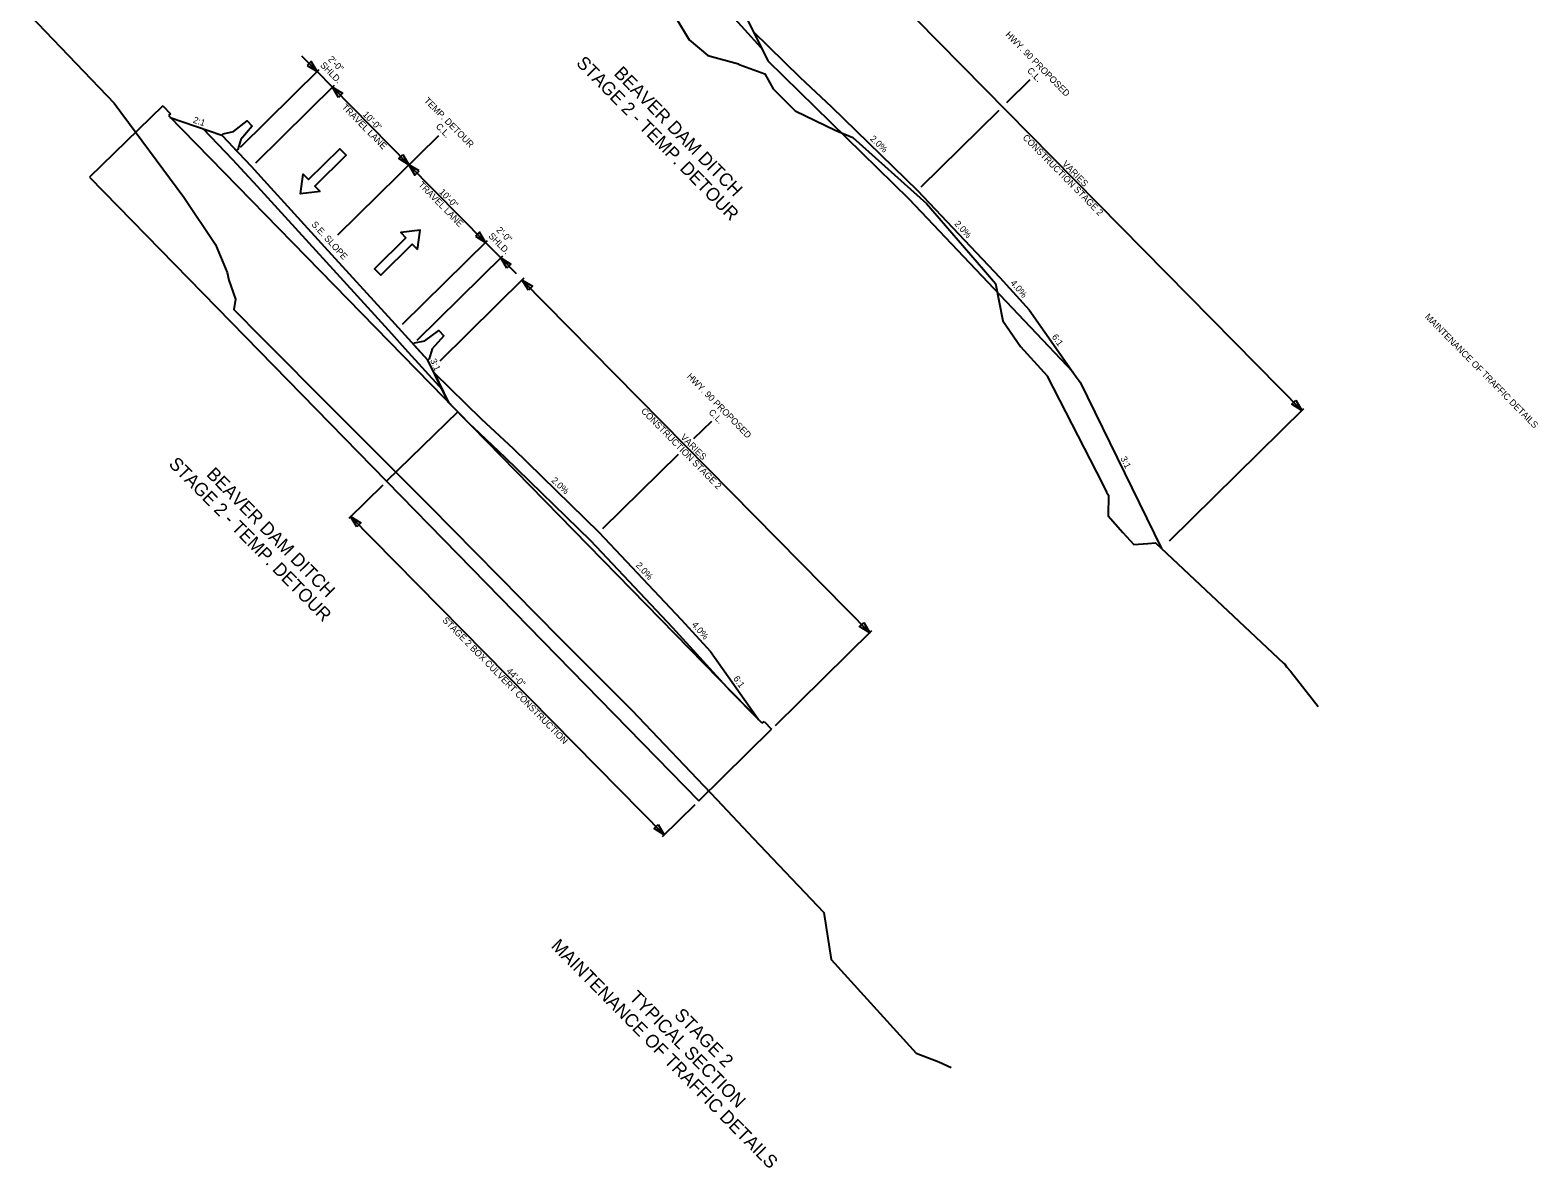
# Model space of a CAD drawing. Extents: x 1660188 to 1660468, y 670370 to 670621.
# Drawn here: x 1660329.3 to 1660467.6, y 670370 to 670474.4 of the extents above; entities that cross this region are included whole.
import ezdxf

# ---------------------------------------------------------------- set-up
doc = ezdxf.new("R2010")
doc.units = 0
for name, color, linetype in [('Default', 7, 'Continuous'), ('R_Annotation', 7, 'Continuous'), ('R_Border', 7, 'Continuous'), ('R_Concrete', 7, 'Continuous'), ('R_Dimension', 7, 'Continuous'), ('R_Exist Surface', 7, 'Continuous'), ('R_Fin Surface', 7, 'Continuous'), ('R_Horz Alg', 7, 'Continuous'), ('R_MOT', 7, 'Continuous')]:
    doc.layers.add(name, color=color, linetype=linetype)

msp = doc.modelspace()

# ---------------------------------------------------------------- linework, layer by layer
at = {"layer": 'Default'}
for points in [[(1660355.93, 670459.59), (1660354.14, 670459.37), (1660354.38, 670461.16), (1660354.87, 670460.67), (1660357.75, 670463.5), (1660358.33, 670462.92), (1660355.44, 670460.08)], [(1660364.87, 670454.24), (1660365.12, 670456.02), (1660363.33, 670455.81), (1660363.81, 670455.32), (1660360.93, 670452.48), (1660361.5, 670451.89), (1660364.39, 670454.73)]]:
    msp.add_lwpolyline(points, close=True, dxfattribs=at)
at = {"layer": 'R_Concrete'}
for p, q in [((1660368.57, 670439.36), (1660362.04, 670432.98)), ((1660396.48, 670410.76), (1660368.57, 670439.36)), ((1660362.04, 670432.98), (1660390.68, 670403.64)), ((1660390.68, 670403.64), (1660397.36, 670410.22)), ((1660396.48, 670410.76), (1660396.66, 670410.94)), ((1660396.66, 670410.94), (1660397.36, 670410.22))]:
    msp.add_line(p, q, dxfattribs=at)
at = {"layer": 'R_Dimension'}
for p, q in [((1660403.83, 670482.3), (1660446, 670439.48)), ((1660355.67, 670470.58), (1660354.27, 670472.01)), ((1660348.64, 670463.66), (1660355.86, 670470.77)), ((1660357.07, 670469.16), (1660355.67, 670470.58)), ((1660350.03, 670462.22), (1660357.26, 670469.34)), ((1660357.07, 670469.16), (1660364.09, 670462.03)), ((1660371.11, 670454.91), (1660364.09, 670462.03)), ((1660363.49, 670447.4), (1660371.29, 670455.09)), ((1660371.11, 670454.91), (1660372.51, 670453.48)), ((1660364.84, 670445.92), (1660372.7, 670453.67)), ((1660372.51, 670453.48), (1660373.91, 670452.06)), ((1660366.94, 670444.02), (1660374.67, 670451.64)), ((1660374.48, 670451.45), (1660406.36, 670419.08)), ((1660433.85, 670427.52), (1660446.19, 670439.67)), ((1660361.68, 670432.63), (1660358.56, 670429.56)), ((1660387.51, 670400.52), (1660358.74, 670429.74)), ((1660397.72, 670410.57), (1660406.55, 670419.27)), ((1660390.32, 670403.29), (1660387.33, 670400.35))]:
    msp.add_line(p, q, dxfattribs=at)
for points in [[(1660354.74, 670471.15), (1660355.67, 670470.58), (1660355.12, 670471.52)], [(1660357.63, 670468.22), (1660357.07, 670469.16), (1660358, 670468.59)], [(1660363.54, 670462.97), (1660364.09, 670462.03), (1660363.16, 670462.6)], [(1660365.02, 670461.46), (1660364.09, 670462.03), (1660364.64, 670461.09)], [(1660370.18, 670455.47), (1660371.11, 670454.91), (1660370.55, 670455.84)], [(1660373.06, 670452.54), (1660372.51, 670453.48), (1660373.44, 670452.91)], [(1660375.04, 670450.52), (1660374.48, 670451.45), (1660375.41, 670450.89)], [(1660445.44, 670440.42), (1660446, 670439.48), (1660445.07, 670440.05)], [(1660359.3, 670428.8), (1660358.74, 670429.74), (1660359.67, 670429.17)], [(1660405.81, 670420.02), (1660406.36, 670419.08), (1660405.43, 670419.65)], [(1660386.96, 670401.46), (1660387.51, 670400.52), (1660386.58, 670401.09)]]:
    msp.add_lwpolyline(points, close=True, dxfattribs=at)
at = {"layer": 'R_Exist Surface'}
for points in [[(1660329.34, 670475.72), (1660337.04, 670467.67), (1660343.43, 670459.06), (1660346.33, 670454.71), (1660347.41, 670452.15), (1660347.57, 670451.45), (1660348.19, 670449.68), (1660348.03, 670448.73), (1660350.57, 670446.17), (1660357.16, 670439.52), (1660361.93, 670434.77), (1660365.98, 670430.71), (1660374.42, 670422.15), (1660375.17, 670421.36), (1660378.52, 670417.98), (1660384.52, 670411.96), (1660392.32, 670403.77), (1660395.67, 670400.21), (1660402.14, 670393.4), (1660402.81, 670389.09), (1660410.61, 670380.49), (1660412.69, 670379.7), (1660413.84, 670379.16)], [(1660388.64, 670475.44), (1660389.79, 670473.5), (1660391.52, 670472.06), (1660394.33, 670471.28), (1660394.38, 670471.22), (1660396.73, 670470.38), (1660397.51, 670469.01), (1660399.52, 670466.98), (1660403.19, 670465.2), (1660404.8, 670464.53), (1660411.57, 670458.46), (1660416.79, 670452.42), (1660417.9, 670451.12), (1660418.57, 670447.69), (1660420.2, 670445.35), (1660422.62, 670442.66), (1660422.62, 670442.63), (1660427.7, 670432.75), (1660428.09, 670431.97), (1660428.26, 670431.71), (1660428.26, 670431.7), (1660428.23, 670429.82), (1660429.59, 670428.26), (1660430.6, 670427.16), (1660431.86, 670427.27), (1660432.58, 670427.34), (1660444.32, 670416.27), (1660444.43, 670416.18), (1660444.59, 670415.94), (1660444.95, 670415.54), (1660447.49, 670412.3)]]:
    msp.add_lwpolyline(points, dxfattribs=at)
at = {"layer": 'R_Fin Surface'}
for p, q in [((1660366.39, 670442.94), (1660367.72, 670440.22)), ((1660367.72, 670440.22), (1660369.7, 670438.19)), ((1660393.53, 670413.78), (1660396.14, 670411.12))]:
    msp.add_line(p, q, dxfattribs=at)
for points in [[(1660395.67, 670474.26), (1660399.94, 670470.08), (1660402.86, 670467.35), (1660410.74, 670459.66), (1660418.3, 670451.67), (1660420.99, 670448.71), (1660425.31, 670442.56), (1660425.65, 670442.07), (1660433.13, 670426.82)], [(1660397, 670471.56), (1660409.96, 670458.9), (1660424.98, 670443.03)], [(1660366.39, 670442.94), (1660370.72, 670438.72), (1660373.64, 670435.98), (1660381.51, 670428.3), (1660389.07, 670420.3), (1660391.76, 670417.34), (1660396.08, 670411.2), (1660396.14, 670411.12)], [(1660369.7, 670438.19), (1660369.97, 670437.94), (1660372.89, 670435.2), (1660380.74, 670427.54), (1660388.28, 670419.57), (1660393.53, 670413.78)]]:
    msp.add_lwpolyline(points, dxfattribs=at)
at = {"layer": 'R_Horz Alg'}
for p, q in [((1660418.95, 670467.75), (1660421.08, 670469.85)), ((1660411.09, 670460.01), (1660418.24, 670467.05)), ((1660357.56, 670455.6), (1660366.83, 670464.73)), ((1660390.23, 670436.89), (1660391.86, 670438.49)), ((1660381.87, 670428.65), (1660388.81, 670435.48))]:
    msp.add_line(p, q, dxfattribs=at)
at = {"layer": 'R_MOT'}
for p, q in [((1660393.38, 670476.1), (1660396.38, 670472.8)), ((1660341.5, 670467.44), (1660334.79, 670460.89)), ((1660341.5, 670467.44), (1660342.2, 670466.72)), ((1660342.2, 670466.72), (1660342.02, 670466.55)), ((1660342.02, 670466.55), (1660368.57, 670439.36)), ((1660334.79, 670460.89), (1660362.04, 670432.98)), ((1660367.72, 670440.22), (1660365.83, 670444.09))]:
    msp.add_line(p, q, dxfattribs=at)
for points in [[(1660341.85, 670523.57), (1660343.03, 670521.18), (1660343.25, 670520.73), (1660347.7, 670511.76), (1660349.52, 670508.08), (1660357.8, 670503.83), (1660369.14, 670498.01), (1660369.35, 670497.91), (1660370.43, 670497.36), (1660374.22, 670495.41), (1660374.89, 670495.06), (1660377.73, 670493.61), (1660378.57, 670493.18), (1660378.95, 670492.78), (1660379.97, 670491.73), (1660383.56, 670487.87), (1660386.83, 670484.36), (1660388.71, 670482.34), (1660393.69, 670477), (1660393.71, 670476.98), (1660394, 670476.66), (1660395.05, 670475.51), (1660395.17, 670475.27), (1660397, 670471.56)], [(1660342.19, 670466.37), (1660346.91, 670464.76), (1660348.49, 670463.09), (1660349.62, 670461.9), (1660350.78, 670460.62), (1660356.35, 670454.5), (1660362.49, 670447.76), (1660363.09, 670447.1), (1660365.83, 670444.09)], [(1660345.22, 670465.34), (1660347.89, 670462.51), (1660349.01, 670461.33), (1660350.17, 670460.06), (1660361.87, 670447.2), (1660362.48, 670446.54), (1660363.72, 670445.17), (1660367.15, 670441.4)], [(1660348.28, 670463.31), (1660347.6, 670464.03), (1660346.91, 670464.76), (1660347.04, 670464.87), (1660347.98, 670465.09), (1660349.24, 670466.05), (1660349.7, 670465.57), (1660348.67, 670464.36), (1660348.4, 670463.43), (1660348.28, 670463.31)], [(1660365.82, 670444.09), (1660365.15, 670444.83), (1660364.48, 670445.57), (1660364.61, 670445.68), (1660365.55, 670445.88), (1660366.84, 670446.82), (1660367.29, 670446.32), (1660366.23, 670445.14), (1660365.94, 670444.21), (1660365.82, 670444.09)]]:
    msp.add_lwpolyline(points, dxfattribs=at)

# ---------------------------------------------------------------- texts
at = {"layer": 'R_Annotation'}
for s, height, rotation, p in [('HWY. 90 PROPOSED', 0.6, 314.5576, (1660418.76, 670473.92)), ('2\'-0"', 0.6, 314.5576, (1660356.62, 670471.66)), ('STAGE 2 - TEMP. DETOUR', 1.2, 314.5226, (1660379.36, 670471.29)), ('SHLD.', 0.6, 314.5576, (1660355.9, 670471.12)), ('BEAVER DAM DITCH', 1.2, 314.5226, (1660382.82, 670470.34)), ('C.L.', 0.6, 314.5576, (1660420.75, 670470.62)), ('TRAVEL LANE', 0.6, 314.5576, (1660357.88, 670467.27)), ('TEMP. DETOUR', 0.6, 314.5576, (1660365.43, 670467.87)), ('2:1', 0.6, 341.1342, (1660344.23, 670465.91)), ('10\'-0"', 0.6, 314.5576, (1660359.8, 670466.6)), ('C.L.', 0.6, 314.5576, (1660366.5, 670465.5)), ('2.0%', 0.6, 316.5576, (1660406.33, 670464.36)), ('CONSTRUCTION STAGE 2', 0.6, 314.5576, (1660420.34, 670464.47)), ('VARIES', 0.6, 314.5576, (1660423.97, 670462.06)), ('TRAVEL LANE', 0.6, 314.5576, (1660364.9, 670460.14)), ('10\'-0"', 0.6, 314.5576, (1660366.81, 670459.48)), ('S.E. SLOPE', 0.6, 312.322, (1660355.1, 670456.52)), ('2.0%', 0.6, 312.5576, (1660414.08, 670456.58)), ('SHLD.', 0.6, 314.5576, (1660371.33, 670455.44)), ('2\'-0"', 0.6, 314.5576, (1660372.06, 670455.99)), ('4.0%', 0.6, 310.5576, (1660419.22, 670451.15)), ('6:1', 0.6, 305.0953, (1660423.03, 670446.23)), ('3:1', 0.6, 293.9898, (1660366.02, 670444.07)), ('HWY. 90 PROPOSED', 0.6, 314.5576, (1660389.54, 670442.55)), ('CONSTRUCTION STAGE 2', 0.6, 314.5576, (1660385.33, 670439.37)), ('C.L.', 0.6, 314.5576, (1660391.53, 670439.25)), ('VARIES', 0.6, 314.5576, (1660388.96, 670436.97)), ('STAGE 2 - TEMP. DETOUR', 1.2, 314.5226, (1660341.98, 670434.49)), ('3:1', 0.6, 296.1227, (1660429.34, 670435.09)), ('BEAVER DAM DITCH', 1.2, 314.5226, (1660345.44, 670433.54)), ('2.0%', 0.6, 316.5576, (1660377.1, 670432.99)), ('2.0%', 0.6, 312.5576, (1660384.86, 670425.22)), ('STAGE 2 BOX CULVERT CONSTRUCTION', 0.6, 314.5576, (1660367.11, 670420.17)), ('4.0%', 0.6, 310.5576, (1660389.99, 670419.78)), ('44\'-0"', 0.6, 314.5576, (1660372.98, 670415.5)), ('6:1', 0.6, 305.0953, (1660393.81, 670414.86)), ('MAINTENANCE OF TRAFFIC DETAILS', 1.2, 314.5576, (1660377.05, 670390.24)), ('TYPICAL SECTION', 1.2, 314.5576, (1660384.22, 670385.52)), ('STAGE 2', 1.2, 314.5576, (1660388.35, 670383.9))]:
    msp.add_text(s, height=height, rotation=rotation, dxfattribs=at).set_placement(p)
at = {"layer": 'R_Border'}
msp.add_text('MAINTENANCE OF TRAFFIC DETAILS', height=0.6, rotation=314.5576, dxfattribs=at).set_placement((1660457.24, 670448.02))

doc.saveas('drawing.dxf')
